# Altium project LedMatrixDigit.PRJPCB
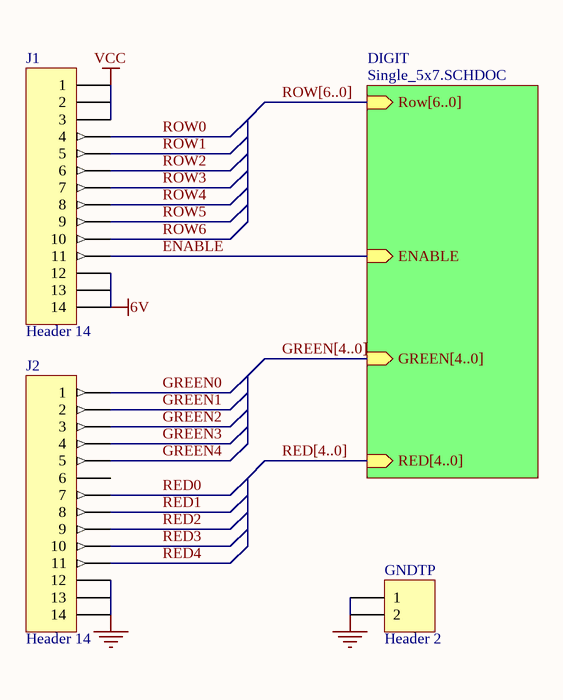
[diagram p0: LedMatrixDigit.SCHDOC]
2 sheets, 43 parts. Net scope: hierarchical (ports join the sheet entries above them; power ports are global).
Board file: LedMatrixDigit.PCBDOC
Sheets:
  LedMatrixDigit.SCHDOC
    DIGIT = Single_5x7.SCHDOC

## Sheet LedMatrixDigit.SCHDOC
size A4

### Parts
GNDTP  Header 2  [HDR1X2]
J1  Header 14  [HDR1X14]
J2  Header 14  [HDR1X14]

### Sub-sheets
DIGIT = Single_5x7.SCHDOC: Row[6..0] (in), ENABLE (in), GREEN[4..0] (in), RED[4..0] (in)

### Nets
6V: J1.12 J1.13 J1.14
GND: GNDTP.1 GNDTP.2 J2.12 J2.13 J2.14
VCC: J1.1 J1.2 J1.3
ENABLE: J1.11 ; sheet DIGIT/ENABLE
GREEN0: J2.1
GREEN1: J2.2
GREEN2: J2.3
GREEN3: J2.4
GREEN4: J2.5
RED0: J2.7
RED1: J2.8
RED2: J2.9
RED3: J2.10
RED4: J2.11
ROW0: J1.4
ROW1: J1.5
ROW2: J1.6
ROW3: J1.7
ROW4: J1.8
ROW5: J1.9
ROW6: J1.10

Not connected (* = marked no-connect by the designer): J2 6

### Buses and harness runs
bus GREEN[4..0] = sheet DIGIT/GREEN[4..0]
bus RED[4..0] = sheet DIGIT/RED[4..0]
bus ROW[6..0] = sheet DIGIT/Row[6..0]

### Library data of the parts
GNDTP = Header 2: Header, 2-Pin; Manufacturer: Generic Components; Class I: Connector; Fitted: True
J1 J2 = Header 14: Header, 14-Pin; Manufacturer: Generic Components; Class I: Connector

## Sheet Single_5x7.SCHDOC
size A4
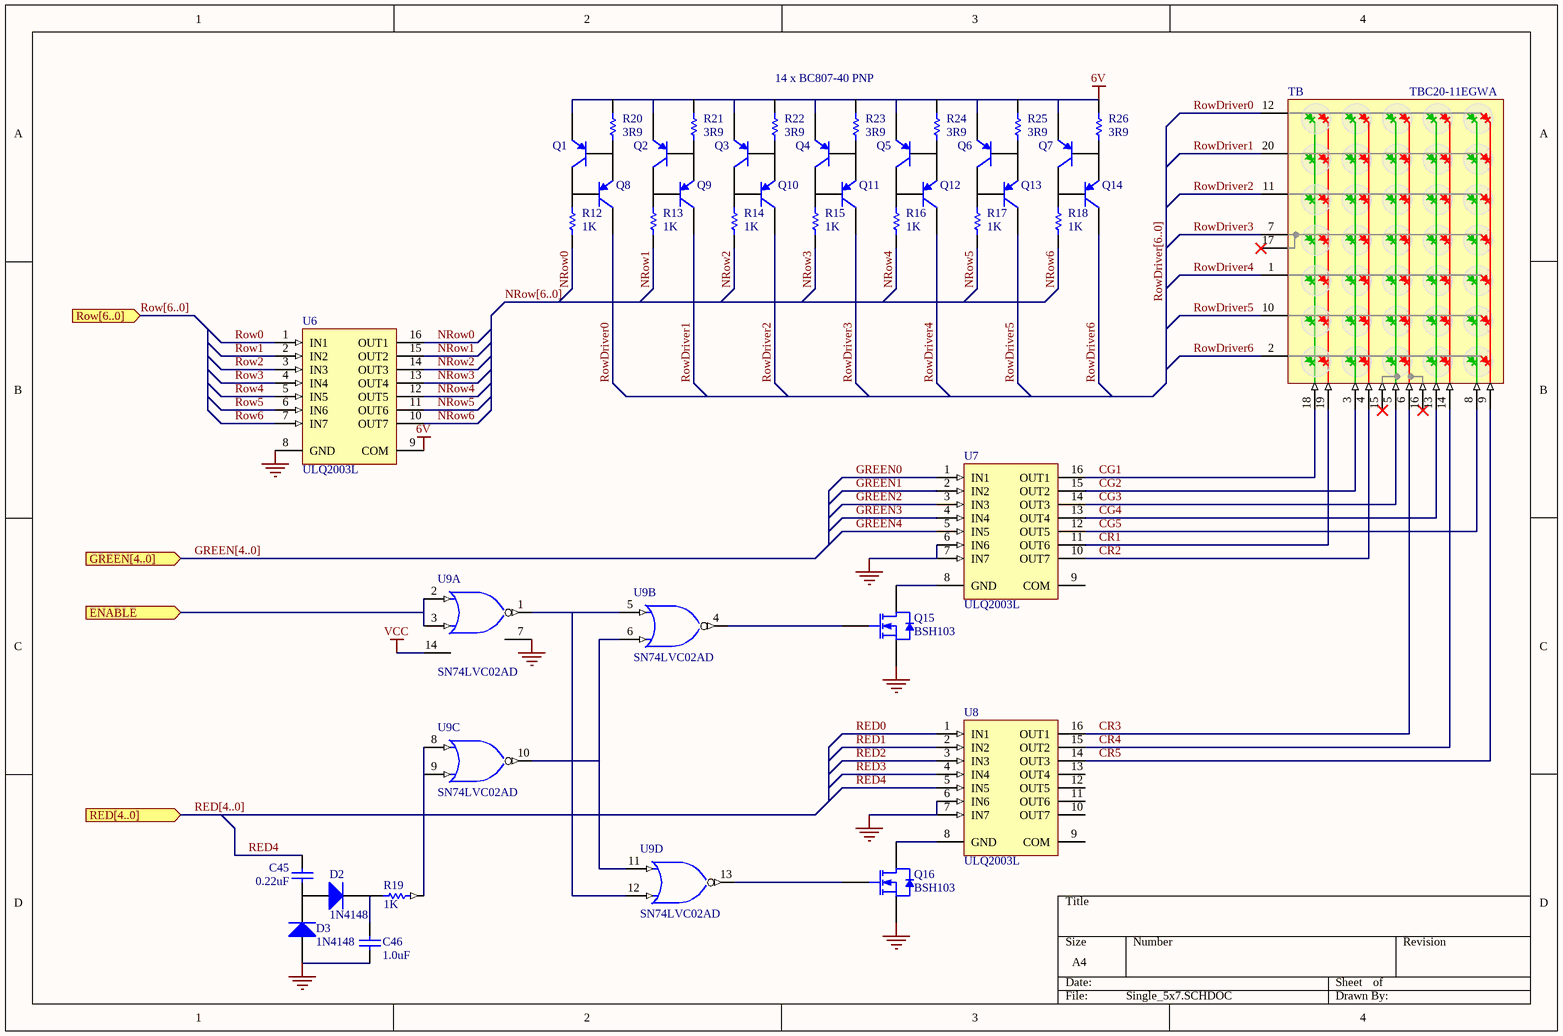
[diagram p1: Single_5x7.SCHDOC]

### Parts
C45  0.22uF  [C3216-1206]
C46  1.0uF  [C3216-1206]
D2  1N4148  [DSO-C2/X3.3]
D3  1N4148  [DSO-C2/X3.3]
Q1  BC807-40  [SOT23]  (value not drawn)
Q2  BC807-40  [SOT23]  (value not drawn)
Q3  BC807-40  [SOT23]  (value not drawn)
Q4  BC807-40  [SOT23]  (value not drawn)
Q5  BC807-40  [SOT23]  (value not drawn)
Q6  BC807-40  [SOT23]  (value not drawn)
Q7  BC807-40  [SOT23]  (value not drawn)
Q8  BC807-40  [SOT23]  (value not drawn)
Q9  BC807-40  [SOT23]  (value not drawn)
Q10  BC807-40  [SOT23]  (value not drawn)
Q11  BC807-40  [SOT23]  (value not drawn)
Q12  BC807-40  [SOT23]  (value not drawn)
Q13  BC807-40  [SOT23]  (value not drawn)
Q14  BC807-40  [SOT23]  (value not drawn)
Q15  BSH103  [SOT23]
Q16  BSH103  [SOT23]
R12  1K  [CC2012-0805]
R13  1K  [CC2012-0805]
R14  1K  [CC2012-0805]
R15  1K  [CC2012-0805]
R16  1K  [CC2012-0805]
R17  1K  [CC2012-0805]
R18  1K  [CC2012-0805]
R19  1K  [CC2012-0805]
R20  3R9  [CC2012-0805]
R21  3R9  [CC2012-0805]
R22  3R9  [CC2012-0805]
R23  3R9  [CC2012-0805]
R24  3R9  [CC2012-0805]
R25  3R9  [CC2012-0805]
R26  3R9  [CC2012-0805]
TB  TBC20-11EGWA  [TBC20-11EGWA]
U6  ULQ2003L  [L16]
U7  ULQ2003L  [L16]
U8  ULQ2003L  [L16]
U9  SN74LVC02AD  [D014]  (parts A,B,C,D of 4)

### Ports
ENABLE (in), GREEN[4..0] (in), RED[4..0] (in), Row[6..0] (in)

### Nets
6V: Q1.2(E) Q2.2(E) Q3.2(E) Q4.2(E) Q5.2(E) Q6.2(E) Q7.2(E) R20.1 R21.1 R22.1 R23.1 R24.1 R25.1 R26.1 U6.9(COM)
GND: C46.1 D3.1(A) Q15.2(S) Q16.2(S) U6.8(GND) U7.6(IN6) U7.7(IN7) U8.6(IN6) U8.7(IN7) U9.7(GND)
VCC: U9.14(VCC)
CG1: TB.18(C1G) U7.16(OUT1)
CG2: TB.3(C2) U7.15(OUT2)
CG3: TB.5(C3G) U7.14(OUT3)
CG4: TB.13(C4G) U7.13(OUT4)
CG5: TB.8(C5G) U7.12(OUT5)
CR1: TB.19(C1R) U7.11(OUT6)
CR2: TB.4(C2R) U7.10(OUT7)
CR3: TB.6(C3R) U8.16(OUT1)
CR4: TB.14(C4R) U8.15(OUT2)
CR5: TB.9(C5R) U8.14(OUT3)
ENABLE: U9.2(A) U9.3(B) ; port ENABLE
GREEN0: U7.1(IN1)
GREEN1: U7.2(IN2)
GREEN2: U7.3(IN3)
GREEN3: U7.4(IN4)
GREEN4: U7.5(IN5)
NRow0: R12.2 U6.16(OUT1)
NRow1: R13.2 U6.15(OUT2)
NRow2: R14.2 U6.14(OUT3)
NRow3: R15.2 U6.13(OUT4)
NRow4: R16.2 U6.12(OUT5)
NRow5: R17.2 U6.11(OUT6)
NRow6: R18.2 U6.10(OUT7)
RED0: U8.1(IN1)
RED1: U8.2(IN2)
RED2: U8.3(IN3)
RED3: U8.4(IN4)
RED4: C45.2 U8.5(IN5)
ROW0: U6.1(IN1)
ROW1: U6.2(IN2)
ROW2: U6.3(IN3)
ROW3: U6.4(IN4)
ROW4: U6.5(IN5)
ROW5: U6.6(IN6)
ROW6: U6.7(IN7)
RowDriver0: Q8.3(C) TB.12(R1)
RowDriver1: Q9.3(C) TB.20(R2)
RowDriver2: Q10.3(C) TB.11(R3)
RowDriver3: Q11.3(C) TB.7(R4)
RowDriver4: Q12.3(C) TB.1(R5)
RowDriver5: Q13.3(C) TB.10(R6)
RowDriver6: Q14.3(C) TB.2(R7)
NetC45_1: C45.1 D2.1(A) D3.2(K)
NetC46_2: C46.2 D2.2(K) R19.1
NetQ1_1: Q1.1(B) Q8.2(E) R20.2
NetQ1_3: Q1.3(C) Q8.1(B) R12.1
NetQ2_1: Q2.1(B) Q9.2(E) R21.2
NetQ2_3: Q2.3(C) Q9.1(B) R13.1
NetQ3_1: Q3.1(B) Q10.2(E) R22.2
NetQ3_3: Q3.3(C) Q10.1(B) R14.1
NetQ4_1: Q4.1(B) Q11.2(E) R23.2
NetQ4_3: Q4.3(C) Q11.1(B) R15.1
NetQ5_1: Q5.1(B) Q12.2(E) R24.2
NetQ5_3: Q5.3(C) Q12.1(B) R16.1
NetQ6_1: Q6.1(B) Q13.2(E) R25.2
NetQ6_3: Q6.3(C) Q13.1(B) R17.1
NetQ7_1: Q7.1(B) Q14.2(E) R26.2
NetQ7_3: Q7.3(C) Q14.1(B) R18.1
NetQ15_1: Q15.1(G) U9.4(Y)
NetQ15_3: Q15.3(D) U7.8(GND)
NetQ16_1: Q16.1(G) U9.13(Y)
NetQ16_3: Q16.3(D) U8.8(GND)
NetR19_2: R19.2 U9.8(A) U9.9(B)
NetU9_1: U9.1(Y) U9.5(A) U9.12(B)
NetU9_6: U9.6(B) U9.10(Y) U9.11(A)

Not connected (* = marked no-connect by the designer): TB 15(C3G)* 16(C3R)* 17(R4)*; U7 9(COM); U8 9(COM) 10(OUT7) 11(OUT6) 12(OUT5) 13(OUT4)

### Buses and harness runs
bus GREEN[4..0] = port GREEN[4..0]
bus NRow[6..0]
bus RED[4..0] = port RED[4..0]
bus Row[6..0] = port Row[6..0]
bus RowDriver[6..0]

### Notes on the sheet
- 14 x BC807-40 PNP

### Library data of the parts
C45 C46 = CAP: Capacitor; Fitted: True
D2 D3 = Diode: Default Diode; Manufacturer: Generic Components; Class I: Discrete; Class II: Diode - Switching
Q1-Q14 = BC807-40: PNP General-purpose Transistor; Manufacturer: Philips Semiconductors; Package Information: Latest Revision: May-1999
Q15 Q16 = BSH103: N-channel Enhancement Mode MOSFET; Manufacturer: Philips Semiconductors; Package Information: Latest Revision: May-1999
R12-R26 = RES: Resistor
U6-U8 = ULQ2003L: High-Voltage, High-Current Darlington Array; Manufacturer: Allegro; Code - JEDEC: MS-012-AC; Code - IPC: SO16
U9 = SN74LVC02AD: Quadruple 2-Input Positive-NOR Gate; Manufacturer: Texas Instruments; Package Information: Latest Revision: Jan-1998

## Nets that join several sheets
6V: LedMatrixDigit (J1.12 J1.13 J1.14), Single_5x7 (15 pins)
GND: LedMatrixDigit (5 pins), Single_5x7 (10 pins)
VCC: LedMatrixDigit (J1.1 J1.2 J1.3), Single_5x7 (U9.14)
ENABLE: LedMatrixDigit (J1.11), Single_5x7 (U9.2 U9.3)
GREEN0: LedMatrixDigit (J2.1), Single_5x7 (U7.1)
GREEN1: LedMatrixDigit (J2.2), Single_5x7 (U7.2)
GREEN2: LedMatrixDigit (J2.3), Single_5x7 (U7.3)
GREEN3: LedMatrixDigit (J2.4), Single_5x7 (U7.4)
GREEN4: LedMatrixDigit (J2.5), Single_5x7 (U7.5)
RED0: LedMatrixDigit (J2.7), Single_5x7 (U8.1)
RED1: LedMatrixDigit (J2.8), Single_5x7 (U8.2)
RED2: LedMatrixDigit (J2.9), Single_5x7 (U8.3)
RED3: LedMatrixDigit (J2.10), Single_5x7 (U8.4)
RED4: LedMatrixDigit (J2.11), Single_5x7 (C45.2 U8.5)
ROW0: LedMatrixDigit (J1.4), Single_5x7 (U6.1)
ROW1: LedMatrixDigit (J1.5), Single_5x7 (U6.2)
ROW2: LedMatrixDigit (J1.6), Single_5x7 (U6.3)
ROW3: LedMatrixDigit (J1.7), Single_5x7 (U6.4)
ROW4: LedMatrixDigit (J1.8), Single_5x7 (U6.5)
ROW5: LedMatrixDigit (J1.9), Single_5x7 (U6.6)
ROW6: LedMatrixDigit (J1.10), Single_5x7 (U6.7)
